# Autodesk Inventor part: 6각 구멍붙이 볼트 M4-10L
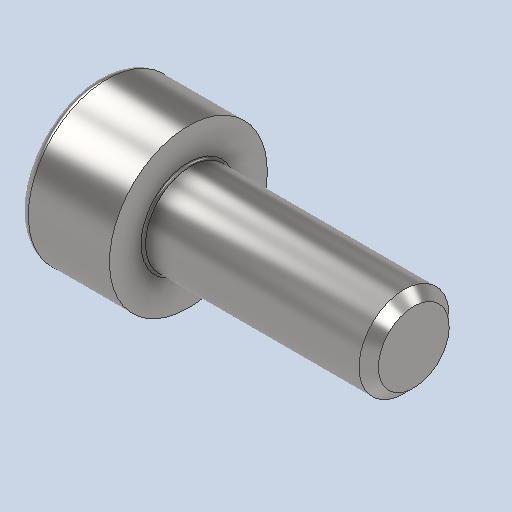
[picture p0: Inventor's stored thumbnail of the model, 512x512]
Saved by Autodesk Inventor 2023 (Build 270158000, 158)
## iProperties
Created: 2025-04
Part Number: 6각 구멍붙이 볼트 M4-10L
Material: 강철, 연강
Description: 6각머리 태핑 나사
Document SubType Name: Modeling
Designer: Admin
Density: 7.86 g/cm^3
Appearance: 기본값
Author: jhkim
Revision Number: 1
Sending System: Autodesk Inventor 2026
Preprocessor: ST-DEVELOPER v20.1
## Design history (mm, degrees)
feature "Solid1"
node "솔리드1"
